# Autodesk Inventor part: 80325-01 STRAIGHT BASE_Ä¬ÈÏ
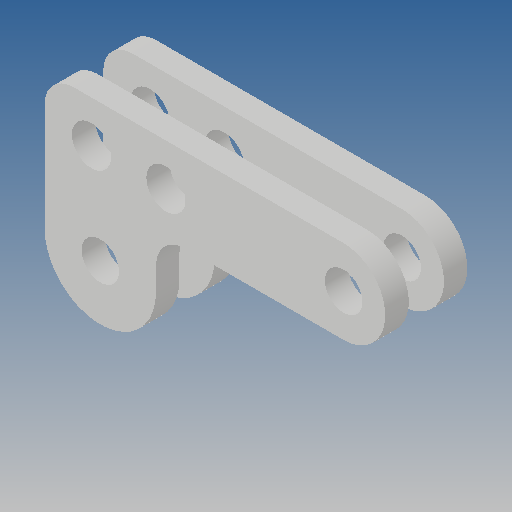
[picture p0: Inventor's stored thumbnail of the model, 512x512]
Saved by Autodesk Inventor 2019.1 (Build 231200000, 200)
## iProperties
Created: 2010-06
Part Number: 80325-01 STRAIGHT BASE_Ä¬ÈÏ
Material: Ogólny
Document SubType Name: Modeling
Designer: CADENGINEERING4
Density: 1 g/cm^3
Appearance: Domyślna
Author: CADENGINEERING4
Revision Number: ÈÎºÎ
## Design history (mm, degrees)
feature "NONE"
feature "NONE:1"
node "Bryła1"
node "Bryła2"
